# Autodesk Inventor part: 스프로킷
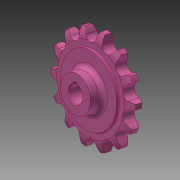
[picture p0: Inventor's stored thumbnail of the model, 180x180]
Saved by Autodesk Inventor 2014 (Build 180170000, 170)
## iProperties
Created: 2016-03
Part Number: 스프로킷
Material: 강철, 탄소
Document SubType Name: Modeling
Designer: mduedu
Density: 7.87 g/cm^3
Mass: 230.696 g
Surface Area: 96.4947 cm^2
Volume: 29.3133 cm^3
Appearance: 분홍색
Author: mduedu
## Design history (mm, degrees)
sketch "스케치1"
  geometry: L1 (0, 5)-(25, 5); L2 (25, 5)-(25, 4.1); L3 (25.5, 3.6)-(29.125, 3.6); L4 (35.5, 2)-(35.5, 0); L5 (35.5, 0)-(0, 0); L6 (0, 0)-(0, 5); L7 (0, -5)-(25, -5); L8 (25, -5)-(25, -4.1); L9 (25.5, -3.6)-(29.125, -3.6); L10 (35.5, -2)-(35.5, 0); L11 (0, 0)-(0, -5); A1 r 13.5 centre (29.125, -9.9) between (35.5, 2) and (29.125, 3.6); A2 r 13.5 centre (29.125, 9.9) between (29.125, -3.6) and (35.5, -2); A3 r 0.5 centre (25.5, 4.1) between (25, 4.1) and (25.5, 3.6); A4 r 0.5 centre (25.5, -4.1) between (25.5, -3.6) and (25, -4.1); 2 further points
  constraints: 22 end point, 8 point on circle, 6 symmetric about line, 5 tangent, 4 centre point, 4 parallel, 4 point on line, 1 equal radius, 1 horizontal, 1 perpendicular, 1 other
  dimensions: "d0" = 71 diameter of L4 L6; "d2" = 50 diameter of L2 L6; "d3" = 1.6 vertical distance of L4.start L3.end; "d4" = 3.6 distance from line of L4.end L3; "d5" = 5 distance between parallel lines of L5 L1; "d6" = 13.5 radius of A1; "d15" = 0.5 radius of A3
revolve "회전1" sketch "스케치1" stored, may be unused: angle "d7" = 90 deg
sketch "스케치2" dims "d8" = 57.16, "d11" = 71
  geometry: L1 (0, 0)-(0, 28.58); A1 r 32.55 centre (0, 0) between (-16.114, 28.281) and (0, 32.55); A2 r 3.97 centre (0, 32.55) between (-3.838, 31.533) and (0, 28.58); A3 r 12.7 centre (-16.114, 28.281) between (-3.838, 31.533) and (-5.392, 35.088); A4 r 12.7 centre (16.114, 28.281) between (5.392, 35.088) and (3.838, 31.533); A5 r 3.97 centre (0, 32.55) between (0, 28.58) and (3.838, 31.533); A6 r 35.5 centre (0, 0) between (5.392, 35.088) and (-5.392, 35.088); 2 further points
  constraints: 12 point on circle, 6 centre point, 4 coincident, 3 symmetric about line, 2 end point, 1 point on line, 1 tangent, 1 vertical, 1 vertical alignment, 7 other
  dimensions: "d10" = 65.1 diameter of A1; "d12" = 12.7 radius of A3
extrude "돌출1" cut sketch "스케치2" stored distance "d13" = 10; taper "d14" = 0 deg
sketch "스케치3"
  geometry: C1 r 11 at (0, 0); 1 further point
  constraints: 1 centre point, 1 coincident
  dimensions: "d19" = 22 diameter of C1
extrude "돌출2" join sketch "스케치3" distance "d20" = 8; taper "d21" = 0 deg
fillet "모깎기1" dims "d22" = 3
sketch "스케치4"
  geometry: L1 (-1.5, 0)-(1.5, 0); L2 (1.5, 0)-(1.5, 6.4); L3 (1.5, 6.4)-(-1.5, 6.4); L4 (-1.5, 6.4)-(-1.5, 0); C1 r 5 at (0, 0); 2 further points
  constraints: 8 end point, 2 coincident, 2 parallel, 1 centre point, 1 horizontal, 1 midpoint, 1 perpendicular
  dimensions: "d23" = 10 diameter of C1; "d25" = 3 distance of L2.end L3.end; "d26" = 6.4 distance of L1.end L2.end
extrude "돌출3" cut sketch "스케치4" stored distance "d27" = 8; taper "d28" = 0 deg
chamfer "모따기1" distance "d29" = 0.5; stored, may be unused: second distance "d30" = 2, angle "d31" = 45 deg
node "솔리드1"
pattern_circular "원형 패턴1" dims angle "d17" = 360 deg
